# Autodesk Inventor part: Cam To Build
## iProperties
Created: 2006-07
Part Number: Cam To Build
Document SubType Name: Modeling
Designer: Maxime Debono
Material: Stainless Steel
Mass: 985.541 g
Surface Area: 287.758 cm^2
Volume: 121.973 cm^3
Density: 8.08 g/cm^3
Author: Maxime Debono
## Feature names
1. Extrusion1
2. Extrusion2
3. Extrusion4
4. Extrusion7
